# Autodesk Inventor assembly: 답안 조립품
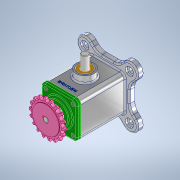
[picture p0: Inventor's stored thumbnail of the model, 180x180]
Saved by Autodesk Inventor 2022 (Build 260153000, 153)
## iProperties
Created: 2022-05
Part Number: 답안 조립품
Document SubType Name: Assembly
Designer: Admin
Author: Admin
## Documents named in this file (11)
- C:\Users\Admin\Desktop\720509V1009\답안 조립품.iam
- C:\Users\Admin\Desktop\720509V1009\본체.ipt
- C:\Users\Admin\Desktop\720509V1009\커버.ipt
- C:\Users\Admin\Desktop\720509V1009\베어링 6203.ipt
- C:\Users\Admin\Desktop\720509V1009\편심축.ipt
- C:\Users\Admin\Desktop\720509V1009\오일 실.ipt
- C:\Users\Admin\Desktop\720509V1009\부시.ipt
- C:\Users\Admin\Desktop\720509V1009\슬라이더.ipt
- C:\Users\Admin\Desktop\720509V1009\키 4 x 4 x 14.ipt
- C:\Users\Admin\Desktop\720509V1009\스프로킷.ipt
- C:\Users\Admin\Desktop\720509V1009\볼트 M4.ipt
